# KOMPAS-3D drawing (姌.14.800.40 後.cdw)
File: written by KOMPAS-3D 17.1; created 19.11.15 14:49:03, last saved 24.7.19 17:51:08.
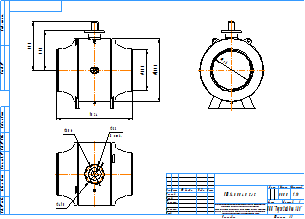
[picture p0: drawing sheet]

Sheet 1: A3, landscape

Title block, sheet 1: name: КШ.14.800.40 С/С; material: Сталь 20  ГОСТ 1050-88; mass: 5800; sheets: 1; sheet format: A3; stored path: C:\Users\kka\KOMPAS_Work\Кран DN800ПП ф. BTL\КШ.14.800.40 сс.cdw

Views: Вид 1
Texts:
  Klimkovich
  ADL
  Рама для чертежей
  Лит-Масса-Масштаб
  Материал-Предприятие
  Масштаб
  Изм.
  Лист
  № докум.
  Подп.
  Дата
  Лит.
  Разраб.
  Пров.
  Т.контр.
  Листов
  Внимание! Данный продукт является объектом авторского права ООО «Торговый Дом АДЛ».
  Запрещается изменение, копирование, распространение
  (в том числе путем копирования на другие сайты и ресурсы в Интернете)
  или любое иное использование информации и объектов без предварительного
  согласия правообладателя (ООО «Торговый Дом АДЛ»).
  Н.контр.
  Утв.
  ООО "Торговый дом АДЛ"
  Изменение
  Номер документа
  Подпись
  Обозначение документа
  Наименование изделия
  Масса изделия по ГОСТ 2.109-73
  Порядковый номер листа
  Общее количество листов в документе
  Характер работы, выполненной лицом, подписавшим документ
  Наименование или индекс предприятия, выпускающего документ
  Инв. № подл.
  Подп. и дата
  Взам. инв. №
  Инв. № дубл.
  Инвентарный номер подлинника по ГОСТ 2.501-68
  Подпись принявшего подлинник в отдел технической документации
  Инвентарный номер подлинника, взамен которого выпущен данный подлинник
  Инвентарный номер дубликата по ГОСТ 2.502-68
  Подпись принявшего дубликат в отдел технической документации
  Справ. №
  Перв. примен.
  Обозначение документа, взамен или на основании которого выпущен данный документ
  Обозначение документа, в котором впервые записан данный документ
  Подпись лица, копировавшего чертеж
  Обозначение формата листа
  !Рама для чертежа
Dimensions and other numbers on the sheet: 1524; 790; 970; 820; 1272; 1:15; 1; 5800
